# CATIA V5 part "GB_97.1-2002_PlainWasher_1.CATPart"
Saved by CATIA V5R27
Part number: GB/T 97.1-2002 平垫圈_1
Bounding box of the stored display mesh (mm): x -6 to 6, y -6 to 6, z 0 to 1.6
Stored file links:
  E:\资料\Catia超级副本\GB 70.1螺钉_带平垫\GB_97.1-2002_PlainWasher_1.CATPart
  E:\资料\Catia超级副本\GB 97.1-2002 平垫圈\GB97.1-2002_PlainWasher_DesignTable.xlsx
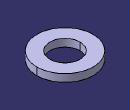
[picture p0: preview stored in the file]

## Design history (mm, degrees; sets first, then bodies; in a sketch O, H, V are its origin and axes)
Parameters
  d1 = 6.4 mm {design table}
  d2 = 12 mm {design table}
  h = 1.6 mm {design table}
  `公称直径d` = 6 mm {design table}
AxisSystem1: origin (0, 0, 0), X (1, 0, 0), Y (0, 1, 0), Z (0, 0, 1)
Set1 "输入参数"
  Point1: (0, 0, 0), in AxisSystem1
  Plane1: type Normal, Curve Line1, RefPoint Point1, Ratio 0
Body1 (main body)
  Sketch1 on Plane1, origin (0, 0, 0), H (1, 0, 0), V (0, 1, 0)
    circle A1 centre (0, 0) radius 3.2
    circle A2 centre (0, 0) radius 6
    radius A1 = 3.2 {= d1 /2}
    radius A2 = 6 {= d2 /2}
    concentricity: A2 A1
  Pad1: profile Sketch1, direction (0, 0, 1), length 1.6 {= h}
  Set2
    Line1: type PtDir, RefPoint Point1, Direction (0, 0, 1), Start 0, End 20
Relations
  design table, configuration 7, drives d1, d2, h, `公称直径d`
